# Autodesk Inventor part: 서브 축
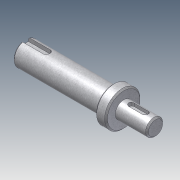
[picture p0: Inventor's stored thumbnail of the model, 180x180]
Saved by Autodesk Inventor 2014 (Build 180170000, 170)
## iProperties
Company: 한국ATC센터
Created: 2014-10
Part Number: 서브 축
Document SubType Name: Modeling
Designer: KYOUNG IL JANG
Density: 7.85 g/cm^3
Mass: 156.705 g
Surface Area: 57.7178 cm^2
Volume: 19.9624 cm^3
Material: 강철
Appearance: 금속-강(스테인리스, 브러시됨)
Author: KYOUNG IL JANG
Revision Number: 1
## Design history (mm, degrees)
sketch "스케치1"
  geometry: L1 (-16.331, 0)-(-108.831, 0); L2 (-16.331, 0)-(-16.331, -6); L3 (-16.331, -6)-(-38.831, -6); L4 (-38.831, -12.5)-(-46.5, -12.5); L5 (-46.5, -8.5)-(-108.831, -8.5); L6 (-108.831, -8.5)-(-108.831, 0); L7 (-46.5, -8.5)-(-46.5, -12.5); L8 (-38.831, -6)-(-38.831, -12.5); L9 (-46.5, 12.249)-(-46.5, -12.249) reference; L10 (-38.831, -17)-(-38.831, 17) reference; 2 further points
  constraints: 17 end point, 4 perpendicular, 2 collinear, 2 parallel, 1 horizontal, 1 midpoint, 1 point on line
  dimensions: "d1" = 12 diameter of L3 L1; "d2" = 25 diameter of L4 L1; "d3" = 17 diameter of L5 L1; "d4" = 62.33128 distance of L5.start L5.end (derived); "d18" = 22.5 distance of L2.end L3.end; "d20" = 70 distance between parallel lines of L6 L8
revolve "회전1" sketch "스케치1" stored, may be unused: angle "d5" = 90 deg
chamfer "모따기1" distance "d6" = 1; stored, may be unused: second distance "d7" = 2, angle "d8" = 45 deg
node "작업 평면1"
sketch "스케치2"
  geometry: L1 (11.25, 5)-(11.25, -5) reference; L2 (-5.75, -2)-(4.25, -2); L3 (4.25, 2)-(-5.75, 2); A1 r 2 centre (4.25, 0) between (4.25, -2) and (4.25, 2); A2 r 2 centre (-5.75, 0) between (-5.75, 2) and (-5.75, -2); 2 further points
  constraints: 4 end point, 4 point on circle, 4 tangent, 2 centre point, 1 horizontal alignment, 1 midpoint, 1 parallel, 1 perpendicular
  dimensions: "d9" = 4 distance between parallel lines of L2 L3; "d10" = 14 dimension on A1 A2; "d11" = 5 distance edge to line of A1 L1
extrude "돌출1" cut sketch "스케치2" distance "d12" = 2.5; taper "d13" = 0 deg
node "작업 평면2"
sketch "스케치3"
  geometry: L1 (-31.166, -7.5)-(-31.166, 7.5) reference; L2 (-31.166, 2.5)-(-15.666, 2.5); L3 (-15.666, -2.5)-(-31.166, -2.5); A1 r 2.5 centre (-15.666, 0) between (-15.666, -2.5) and (-15.666, 2.5); 2 further points
  constraints: 4 end point, 2 perpendicular, 2 point on circle, 2 point on line, 2 tangent, 1 centre point, 1 horizontal alignment, 1 midpoint
  dimensions: "d14" = 5 distance between parallel lines of L3 L2; "d15" = 18 dimension on A1 L1
extrude "돌출2" cut sketch "스케치3" distance "d16" = 3; taper "d17" = 0 deg
node "솔리드1"
node "참조4"
node "참조5"
